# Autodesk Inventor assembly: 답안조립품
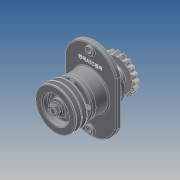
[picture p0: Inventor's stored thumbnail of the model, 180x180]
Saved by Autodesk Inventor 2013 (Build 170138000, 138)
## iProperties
Created: 2015-02
Part Number: 답안조립품
Document SubType Name: Assembly
Designer: kb543-18
Author: kb543-18
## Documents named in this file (12)
- C:\Users\kb543-18\Desktop\450207V1025\답안조립품.iam
- C:\Users\kb543-18\Desktop\450207V1025\1-본체.ipt
- C:\Users\kb543-18\Desktop\450207V1025\2-커버.ipt
- C:\Users\kb543-18\Desktop\450207V1025\3-축.ipt
- C:\Users\kb543-18\Desktop\450207V1025\4-V벨트풀리.ipt
- C:\Users\kb543-18\Desktop\450207V1025\5-체인 스프로킷.ipt
- C:\Users\kb543-18\Desktop\450207V1025\7-부시.ipt
- C:\Users\kb543-18\Desktop\450207V1025\6-베어링 6206.ipt
- C:\Users\kb543-18\Desktop\450207V1025\8-오일실 30x42.ipt
- C:\Users\kb543-18\Desktop\450207V1025\9-M16-너트.ipt
- C:\Users\kb543-18\Desktop\450207V1025\11-키 6x6.ipt
- C:\Users\kb543-18\Desktop\450207V1025\10-M6.ipt
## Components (23 placed, 11 different names)
1. 1-본체:1
2. 2-커버:1
3. 2-커버:2
4. 3-축:1
5. 4-V벨트풀리:1
6. 5-체인 스프로킷:1
7. 7-부시:1
8. 6-베어링 6206:1
9. 8-8-오일실 30x42:1
10. 9-M16 너트:1
11. 11-키 6x6:1
12. 6-베어링 6206:2
13. 8-8-오일실 30x42:2
14. 9-M16 너트:2
15. 11-키 6x6:2
16. 10-M6:1
17. 10-M6:2
18. 10-M6:3
19. 10-M6:4
20. 10-M6:5
21. 10-M6:6
22. 10-M6:7
23. 10-M6:8
